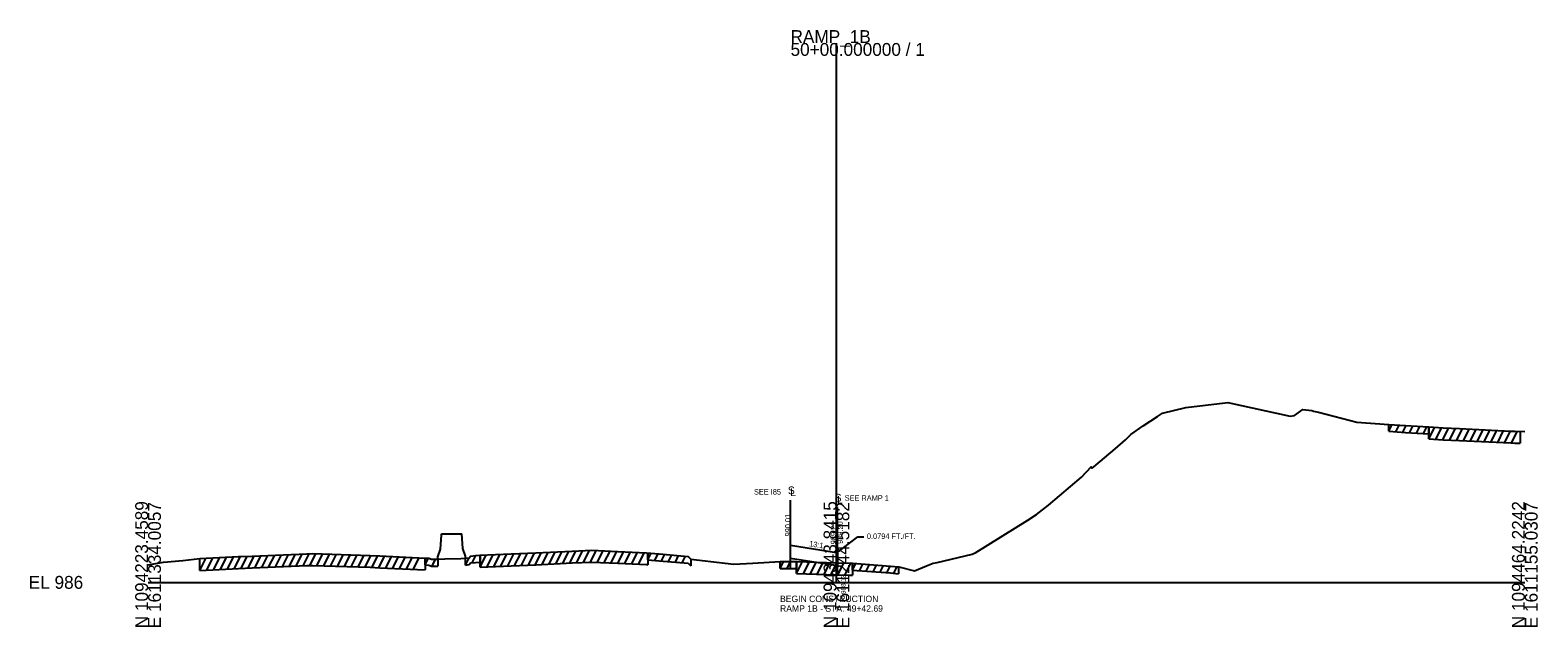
# Model space of a CAD drawing. Extents: x -26 to 1615461, y 490 to 1281970.
# Drawn here: x -25.7 to 302.8, y 490.3 to 620.3 of the extents above; entities that cross this region are included whole.
import ezdxf

# ---------------------------------------------------------------- set-up
doc = ezdxf.new("R2010")
doc.units = 0
for name, color, linetype in [('RD_EX_Misc', 7, 'Continuous'), ('RD_GPK_XS_Cell', 7, 'Continuous'), ('RD_Sketch1', 7, 'Continuous'), ('RD_XE_Ground', 7, 'Continuous'), ('RD_XS_Base', 7, 'Continuous'), ('RD_XS_ExGround', 7, 'Continuous'), ('RD_XS_ExPaveRet', 7, 'Continuous'), ('RD_XS_MatchLine', 7, 'Continuous'), ('RD_XS_Pave', 7, 'Continuous'), ('RD_XS_PaveShd', 7, 'Continuous'), ('RD_XS_TX_Elev_EX', 7, 'Continuous'), ('RD_XS_TX_Elev_PR', 7, 'Continuous'), ('RD_XS_TX_MatchLine', 7, 'Continuous'), ('RD_XS_TX_Notes', 7, 'Continuous'), ('RD_XS_TX_ShdSlope', 7, 'Continuous'), ('RD_XS_TX_Slope', 7, 'Continuous')]:
    doc.layers.add(name, color=color, linetype=linetype)

msp = doc.modelspace()

# ---------------------------------------------------------------- linework, layer by layer
at = {"layer": 'RD_EX_Misc'}
for p, q in [((270.4, 532.91), (270.4, 534.41)), ((270.4, 532.91), (274, 532.65)), ((274, 532.65), (279.12, 532.35)), ((279.12, 533.85), (279.12, 532.35)), ((108.9, 504.93), (108.9, 506.43)), ((60.39, 503.8), (60.39, 505.3)), ((60.39, 503.8), (61.19, 503.76)), ((61.19, 503.76), (61.78, 503.52)), ((61.78, 503.52), (62.57, 503.54)), ((62.57, 503.54), (62.93, 503.52)), ((62.93, 503.52), (63.16, 503.54)), ((63.16, 505.04), (63.16, 503.54)), ((69.14, 503.74), (69.14, 505.24)), ((69.14, 503.74), (69.17, 503.74)), ((69.17, 503.74), (69.97, 503.87)), ((69.97, 503.87), (70.28, 504.23)), ((70.28, 504.23), (71.38, 504.34)), ((71.38, 504.34), (72.28, 504.42)), ((72.28, 504.42), (72.38, 504.43)), ((72.38, 505.93), (72.38, 504.43)), ((108.9, 504.93), (111.35, 504.72)), ((111.35, 504.72), (117.7, 504.16)), ((117.7, 504.16), (118.26, 503.57)), ((118.26, 505.07), (118.26, 503.57)), ((137.75, 503.01), (137.75, 504.51)), ((137.75, 503.01), (139.06, 503.02)), ((139.06, 503.02), (141.33, 503.05)), ((141.33, 504.55), (141.33, 503.05)), ((153.5, 502.65), (153.5, 504.15)), ((163.52, 503.39), (163.52, 501.89)), ((153.5, 502.65), (161.79, 502.04)), ((161.79, 502.04), (163.52, 501.89))]:
    msp.add_line(p, q, dxfattribs=at)
at = {"layer": 'RD_GPK_XS_Cell'}
for p, q in [((150, 500), (150, 617.51)), ((0, 500), (150, 500)), ((150, 500), (300, 500))]:
    msp.add_line(p, q, dxfattribs=at)
at = {"layer": 'RD_Sketch1'}
for p, q in [((270.4, 532.91), (271.13, 534.36)), ((271.9, 532.8), (272.63, 534.25)), ((273.4, 532.69), (274.13, 534.14)), ((274.9, 532.59), (275.63, 534.05)), ((276.4, 532.51), (277.13, 533.97)), ((277.9, 532.42), (278.63, 533.88)), ((108.9, 504.93), (109.62, 506.37)), ((110.4, 504.81), (111.12, 506.24)), ((111.9, 504.68), (112.62, 506.11)), ((113.4, 504.54), (114.12, 505.98)), ((60.39, 503.8), (61.13, 505.27)), ((61.89, 503.52), (62.65, 505.03)), ((69.14, 503.74), (69.95, 505.37)), ((70.64, 504.26), (71.43, 505.85)), ((114.9, 504.41), (115.62, 505.84)), ((116.4, 504.28), (117.12, 505.71)), ((137.75, 503.01), (138.5, 504.52)), ((139.25, 503.03), (140, 504.53)), ((153.5, 502.65), (154.22, 504.1)), ((155, 502.54), (155.72, 503.99)), ((156.5, 502.43), (157.22, 503.88)), ((158, 502.32), (158.72, 503.76)), ((159.5, 502.21), (160.22, 503.65)), ((161, 502.1), (161.72, 503.54)), ((162.5, 501.98), (163.22, 503.42))]:
    msp.add_line(p, q, dxfattribs=at)
at = {"layer": 'RD_XE_Ground'}
for p, q in [((63.74, 507.2), (63.91, 510.37)), ((63.91, 510.58), (68.39, 510.58)), ((63.91, 510.37), (63.91, 510.58)), ((68.56, 507.41), (68.39, 510.58)), ((63.16, 505.54), (63.74, 507.2)), ((69.14, 505.74), (68.56, 507.41)), ((63.16, 505.04), (63.16, 505.54)), ((69.14, 505.24), (69.14, 505.74))]:
    msp.add_line(p, q, dxfattribs=at)
at = {"layer": 'RD_XS_Base'}
for p, q in [((150.2, 506.39), (150.2, 503.61)), ((150.2, 503.61), (140, 505.23))]:
    msp.add_line(p, q, dxfattribs=at)
at = {"layer": 'RD_XS_ExGround'}
msp.add_lwpolyline([(0, 503.83), (3.37, 504.37), (7.56, 504.79), (11.28, 505.17), (19.72, 505.6), (22.67, 505.74), (34.58, 506.24), (35.81, 506.27), (48.37, 505.88), (50.52, 505.77), (60.39, 505.3), (61.19, 505.26), (61.78, 505.02), (62.57, 505.04), (62.93, 505.02), (64.66, 505.15), (68.18, 505.19), (69.17, 505.24), (69.97, 505.37), (70.28, 505.73), (71.38, 505.84), (72.28, 505.92), (79.12, 506.21), (84.52, 506.45), (92.39, 506.82), (96.69, 507.02), (102.33, 506.75), (108.62, 506.46), (111.35, 506.22), (117.7, 505.66), (118.26, 505.07), (125.74, 504.19), (127.65, 503.95), (131.78, 504.17), (137.75, 504.51), (139.06, 504.52), (141.33, 504.55), (150, 504.26), (152.95, 504.17), (153.5, 504.15), (161.79, 503.54), (163.63, 503.38), (167.02, 502.52), (169.6, 503.58), (171.09, 504.21), (171.97, 504.33), (179.58, 506.11), (180.35, 506.53), (191.7, 513.57), (193.58, 514.8), (196.18, 516.84), (203.37, 522.92), (205.51, 525.17), (205.7, 524.85), (206.07, 525.16), (210.73, 529.1), (213.02, 531.05), (214.17, 532.24), (216.83, 534.12), (219.94, 536.1), (221.05, 536.83), (226.1, 538.12), (234.68, 539.13), (235.3, 539.17), (248.87, 536.18), (249.78, 536.36), (251.66, 537.69), (253.59, 537.41), (253.98, 537.27), (255.02, 537.09), (263.43, 534.91), (270.38, 534.41), (274, 534.15), (279.12, 533.85), (282.19, 533.67), (285.74, 533.49), (296.98, 532.97), (297.82, 532.94), (300, 532.87)], dxfattribs=at)
at = {"layer": 'RD_XS_ExPaveRet'}
for p, q in [((279.12, 531.25), (279.12, 533.85)), ((279.12, 531.25), (280.38, 533.78)), ((280.62, 531.16), (281.88, 533.69)), ((282.12, 531.07), (283.39, 533.61)), ((283.62, 531), (284.89, 533.53)), ((285.12, 530.92), (286.39, 533.46)), ((286.62, 530.85), (287.89, 533.39)), ((288.12, 530.78), (289.39, 533.32)), ((289.62, 530.71), (290.89, 533.25)), ((291.12, 530.64), (292.39, 533.18)), ((292.62, 530.57), (293.89, 533.12)), ((294.12, 530.5), (295.39, 533.05)), ((295.62, 530.44), (296.89, 532.98)), ((297.12, 530.37), (298.4, 532.92)), ((298.99, 532.91), (298.99, 530.31)), ((279.12, 531.25), (282.19, 531.07)), ((279.12, 531.25), (279.12, 531.25)), ((282.19, 531.07), (285.74, 530.89)), ((285.74, 530.89), (296.98, 530.37)), ((296.98, 530.37), (297.82, 530.34)), ((297.82, 530.34), (298.99, 530.31)), ((26.28, 503.29), (27.61, 505.95)), ((27.78, 503.35), (29.11, 506.01)), ((29.28, 503.42), (30.61, 506.07)), ((30.78, 503.48), (32.11, 506.13)), ((32.28, 503.54), (33.61, 506.2)), ((33.78, 503.6), (35.1, 506.25)), ((35.28, 503.66), (36.57, 506.25)), ((36.78, 503.64), (38.06, 506.2)), ((38.28, 503.59), (39.56, 506.15)), ((39.78, 503.55), (41.06, 506.11)), ((41.28, 503.5), (42.56, 506.06)), ((42.78, 503.45), (44.06, 506.01)), ((44.28, 503.4), (45.56, 505.96)), ((72.38, 503.33), (73.71, 505.98)), ((73.88, 503.39), (75.21, 506.05)), ((75.38, 503.45), (76.71, 506.11)), ((76.88, 503.52), (78.21, 506.18)), ((78.38, 503.58), (79.71, 506.24)), ((79.88, 503.65), (81.21, 506.31)), ((81.38, 503.71), (82.71, 506.37)), ((82.88, 503.78), (84.21, 506.44)), ((84.38, 503.84), (85.71, 506.5)), ((85.88, 503.91), (87.22, 506.57)), ((87.38, 503.98), (88.72, 506.64)), ((88.88, 504.05), (90.22, 506.71)), ((90.38, 504.12), (91.72, 506.78)), ((91.88, 504.19), (93.22, 506.85)), ((93.38, 504.26), (94.72, 506.92)), ((94.88, 504.33), (96.22, 506.99)), ((96.38, 504.4), (97.67, 506.97)), ((97.88, 504.36), (99.16, 506.9)), ((99.38, 504.29), (100.66, 506.83)), ((100.88, 504.22), (102.16, 506.76)), ((102.38, 504.15), (103.65, 506.69)), ((103.88, 504.08), (105.15, 506.62)), ((105.38, 504.01), (106.65, 506.55)), ((106.89, 503.94), (108.16, 506.48)), ((108.9, 506.43), (108.9, 503.83)), ((11.28, 502.57), (12.61, 505.23)), ((11.28, 502.57), (11.28, 505.17)), ((11.28, 502.57), (19.72, 503)), ((12.78, 502.64), (14.11, 505.31)), ((14.28, 502.72), (15.61, 505.39)), ((15.78, 502.8), (17.11, 505.46)), ((17.28, 502.87), (18.61, 505.54)), ((18.78, 502.95), (20.11, 505.62)), ((19.72, 503), (22.67, 503.14)), ((20.28, 503.02), (21.61, 505.69)), ((21.78, 503.1), (23.11, 505.76)), ((22.67, 503.14), (34.58, 503.64)), ((23.28, 503.17), (24.61, 505.82)), ((24.78, 503.23), (26.11, 505.88)), ((34.58, 503.64), (35.81, 503.67)), ((35.81, 503.67), (48.37, 503.28)), ((45.78, 503.36), (47.06, 505.92)), ((47.28, 503.31), (48.56, 505.87)), ((48.37, 503.28), (50.52, 503.17)), ((48.78, 503.26), (50.05, 505.79)), ((50.28, 503.18), (51.55, 505.72)), ((50.52, 503.17), (60.39, 502.7)), ((51.78, 503.11), (53.05, 505.65)), ((53.28, 503.04), (54.55, 505.58)), ((54.78, 502.97), (56.05, 505.51)), ((56.28, 502.9), (57.55, 505.44)), ((57.78, 502.83), (59.05, 505.36)), ((60.39, 505.3), (60.39, 502.7)), ((72.38, 503.33), (72.38, 505.93)), ((72.38, 503.33), (79.12, 503.61)), ((79.12, 503.61), (84.52, 503.85)), ((84.52, 503.85), (92.39, 504.22)), ((92.39, 504.22), (96.69, 504.42)), ((96.69, 504.42), (102.33, 504.15)), ((102.33, 504.15), (108.62, 503.86)), ((108.62, 503.86), (108.9, 503.83)), ((141.33, 501.95), (141.33, 504.55)), ((141.33, 501.95), (142.61, 504.51)), ((142.83, 501.9), (144.11, 504.46)), ((144.33, 501.85), (145.61, 504.41)), ((145.83, 501.8), (147.11, 504.36)), ((147.33, 501.75), (148.61, 504.31)), ((148.83, 501.7), (150.11, 504.26)), ((150.33, 501.65), (151.61, 504.21)), ((151.83, 501.6), (153.11, 504.16)), ((153.5, 504.15), (153.5, 501.55)), ((141.33, 501.95), (150, 501.66)), ((150, 501.66), (152.95, 501.57)), ((152.95, 501.57), (153.5, 501.55))]:
    msp.add_line(p, q, dxfattribs=at)
at = {"layer": 'RD_XS_MatchLine'}
for p, q in [((140, 504.53), (140, 508.01)), ((150.2, 504.26), (150.2, 506.39))]:
    msp.add_line(p, q, dxfattribs=at)
at = {"layer": 'RD_XS_Pave'}
msp.add_line((150, 506.42), (150.2, 506.39), dxfattribs=at)
at = {"layer": 'RD_XS_PaveShd'}
msp.add_line((150, 506.42), (140, 508.01), dxfattribs=at)
msp.add_line((150, 506.42), (140, 508.01), dxfattribs=at)
at = {"layer": 'RD_XS_TX_Elev_PR'}
for p, q in [((150.1, 506.41), (154.66, 509.91)), ((154.66, 509.91), (155.97, 509.91))]:
    msp.add_line(p, q, dxfattribs=at)
at = {"layer": 'RD_XS_TX_MatchLine'}
for p, q in [((140, 508.01), (140, 517.9)), ((150.2, 506.39), (150.2, 516.28)), ((140, 503.01), (140, 508.01)), ((150.2, 501.39), (150.2, 506.39))]:
    msp.add_line(p, q, dxfattribs=at)

# ---------------------------------------------------------------- texts
at = {"layer": 'RD_GPK_XS_Cell'}
for s, p in [('50+00.000000 / 1', (140, 614.71)), ('RAMP_1B', (140, 617.51)), ('EL 986', (-26, 498.6))]:
    msp.add_text(s, height=2.8, dxfattribs=at).set_placement(p)
for s, p in [('N 1094223.4589', (0, 490)), ('E 1611334.0057', (2.8, 490)), ('N 1094343.8415', (150, 490)), ('E 1611244.5182', (152.8, 490)), ('N 1094464.2242', (300, 490)), ('E 1611155.0307', (302.8, 490))]:
    msp.add_text(s, height=2.8, rotation=90, dxfattribs=at).set_placement(p)
at = {"layer": 'RD_XS_TX_Elev_EX'}
msp.add_text('988.13', height=1, rotation=90, dxfattribs=at).set_placement((152, 497.46))
at = {"layer": 'RD_XS_TX_Elev_PR'}
for s, p in [('990.01', (140, 510.01)), ('989.21', (149.95, 508.29)), ('989.20', (151.4, 508.39))]:
    msp.add_text(s, height=1.2, rotation=90, dxfattribs=at).set_placement(p)
at = {"layer": 'RD_XS_TX_MatchLine'}
for s, p in [('S', (139.42, 519.21)), ('L', (139.93, 518.78)), ('S', (149.61, 517.59)), ('L', (150.13, 517.16))]:
    msp.add_text(s, height=1.68, dxfattribs=at).set_placement(p)
at = {"layer": 'RD_XS_TX_Notes'}
for s, p in [('SEE I85', (132.03, 519.12)), ('SEE RAMP 1', (151.79, 517.78))]:
    msp.add_text(s, height=1.2, rotation=360, dxfattribs=at).set_placement(p)
for s, p in [('BEGIN CONSTRUCTION', (137.71, 495.7)), ('RAMP 1B - STA. 49+42.69', (137.71, 493.6))]:
    msp.add_text(s, height=1.4, dxfattribs=at).set_placement(p)
at = {"layer": 'RD_XS_TX_ShdSlope'}
msp.add_text('13:1', height=1.2, rotation=350.9756, dxfattribs=at).set_placement((144, 507.88))
msp.add_text('13:1', height=1.2, rotation=350.9756, dxfattribs=at).set_placement((144, 507.88))
at = {"layer": 'RD_XS_TX_Slope'}
msp.add_text('0.0794 FT./FT.', height=1.2, dxfattribs=at).set_placement((156.64, 509.45))

doc.saveas('drawing.dxf')
